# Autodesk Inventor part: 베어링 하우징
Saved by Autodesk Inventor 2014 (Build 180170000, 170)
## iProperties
Created: 2026-05
Part Number: 베어링 하우징
Material: 일반
Document SubType Name: Modeling
Designer: dg
Density: 1 g/cm^3
Appearance: 기본값
Author: dg
Author: jhkim
Creation Date: 2026-04-23
Sending System: Autodesk Inventor 2027
Preprocessor: ST-DEVELOPER v20.1
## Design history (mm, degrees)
node "베어링 하우징1"
node "솔리드1"
node "기준1"
